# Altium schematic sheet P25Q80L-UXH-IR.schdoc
size 127 x 101 mm
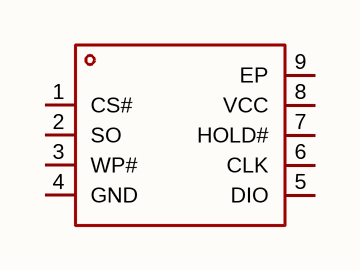
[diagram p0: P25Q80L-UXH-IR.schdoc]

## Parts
U?  p25q80l-uxh-ir  [USON-8_L3.0-W2.0-P0.50-BL-EP_P25XX]  (value not drawn)

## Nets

Not connected (* = marked no-connect by the designer): U? 1(CS#) 2(SO) 3(WP#) 4(GND) 5(DIO) 6(CLK) 7(HOLD#) 8(VCC) 9(EP)

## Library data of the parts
U? = p25q80l-uxh-ir: 接口类型:SPI;存储容量:8Mbit;时钟频率(fc):85MHz;; Manufacturer: PUYA(普冉); AddInBom: yes; ModelId: 12a239e5c7384371915ecb51201bf581; ModelName: USON-8_L3.0-W2.0-H0.6-P0.50; ModelTransform: 118.8974,78.74,0,90,0,0,0,0,0; Interface: SPI; Memory Size: 8Mbit; Clock Frequency: 85MHz; Voltage - Supply: 1.65V~2V; Standby Supply Current: 6uA; Program / Erase Cycles: 100000次; Page Programming Time (Tpp): 2ms; Data Retention - TDR (Year): 20年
